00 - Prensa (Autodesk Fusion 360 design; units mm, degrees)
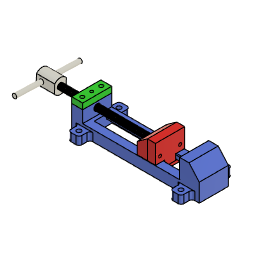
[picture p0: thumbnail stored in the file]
parameter "d29" = 2.5
sketch "Boceto1" plane through (0, 0, 0) normal (0, 1, 0) x axis (1, 0, 0)
  line L1 (175, 0) -> (0, 0)
  line L2 (0, -40) -> (0, 0)
  line L3 (15, -40) -> (0, -40)
  line L4 (15, -14) -> (15, -40)
  line L5 (151, -14) -> (15, -14)
  line L6 (151, -40) -> (151, -14)
  line L7 (161, -40) -> (151, -40)
  line L8 (175, -14) -> (175, 0)
  line L9 (175, -24) -> (175, -14)
  line L10 (161, -40) -> (175, -24)
  point P1 (0, 0)
  point P2 (0, 0)
  point P4 (0, 0)
  point P3 (175, 0)
  point P5 (0, -40)
  point P6 (15, -40)
  point P7 (15, -14)
  point P8 (151, -14)
  point P9 (151, -40)
  point P10 (161, -40)
  point P11 (175, -14)
  point P12 (175, -24)
  coincident P1 P2
  horizontal L1
  coincident P1 P4
  perpendicular L1 L2
  perpendicular L2 L3
  perpendicular L3 L4
  perpendicular L4 L5
  perpendicular L3 L6
  perpendicular L6 L7
  perpendicular L5 L8
  perpendicular L5 L9
  dimension "d1" distance P2 P3 = 175
  dimension "d2" distance P4 P5 = 40
  dimension "d3" distance P5 P6 = 15
  dimension "d4" distance P6 P7 = 26
  dimension "d5" distance P7 P8 = 136
  dimension "d7" distance P9 P10 = 10
  dimension "d8" distance P11 P12 = 10
extrude "Extruir1" new body sketch "Boceto1" along normal blind 40
sketch "Boceto2" plane through (0, 0, 14) normal (0, 0, 1) x axis (-1, 0, 0)
  line L1 (-151, 0) -> (-15, 0)
  line L2 (-151, -40) -> (-151, 0)
  line L3 (-15, -40) -> (-151, -40)
  line L4 (-15, 0) -> (-15, -40)
  line L5 (-146, -27.5) -> (-20, -27.5)
  line L6 (-146, -12.5) -> (-146, -27.5)
  line L7 (-20, -12.5) -> (-146, -12.5)
  line L8 (-20, -27.5) -> (-20, -12.5)
  line L9 (-146, -12.5) -> (-20, -27.5)
  line L10 (-20, -12.5) -> (-146, -27.5)
  line L11 (-83, 0) -> (-83, -40)
  point P10 (-83, -20)
  point P11 (-83, -40)
  point P12 (-83, 0)
  point P8 (-146, -12.5)
  point P9 (-20, -12.5)
  point P7 (-146, -27.5)
  horizontal L5
  perpendicular L5 L6
  parallel L5 L7
  parallel L6 L8
  coincident L9 P10
  coincident L10 P10
  midpoint L3 P11
  midpoint L1 P12
  midpoint P10 L11
  dimension "d11" distance P8 P9 = 126
  dimension "d12" distance P7 P8 = 15
extrude "Extruir2" cut sketch "Boceto2" profile of L5 L6 L7 L8 against normal blind 14
sketch "Boceto3" plane through (0, 0, 0) normal (-1, 0, 0) x axis (0, -1, 0)
  line L1 (0, 40) -> (0, 0)
  line L2 (-40, 40) -> (0, 40)
  line L3 (-40, 0) -> (-40, 40)
  line L4 (0, 0) -> (-40, 0)
  line L5 (-20, 23) -> (-20, 40)
  circle C1 centre (-20, 23) radius 4
  point P6 (-20, 40)
  point P7 (-20, 23)
  point P8 (-20, 23)
  midpoint L2 P6
  perpendicular L2 L5
  coincident P7 P8
  dimension "d15" distance P6 P7 = 17
  dimension "d16" diameter C1 = 8
extrude "Extruir3" cut sketch "Boceto3" profile of C1 against normal blind 15
sketch "Boceto4" plane through (0, 0, 0) normal (0, 0, -1) x axis (1, 0, 0)
  line L1 (146, -27.5) -> (146, -12.5)
  line L2 (20, -27.5) -> (146, -27.5)
  line L3 (20, -12.5) -> (20, -27.5)
  line L4 (146, -12.5) -> (20, -12.5)
  line L5 (0, 0) -> (175, 0)
  line L6 (0, -40) -> (0, 0)
  line L7 (175, -40) -> (0, -40)
  line L8 (175, 0) -> (175, -40)
  line L9 (20, -5) -> (146, -5)
  line L10 (20, -35) -> (20, -5)
  line L11 (146, -35) -> (20, -35)
  line L12 (146, -5) -> (146, -35)
  line L13 (20, -35) -> (146, -5)
  line L14 (146, -35) -> (20, -5)
  point P14 (83, -20)
  point P12 (20, -35)
  point P13 (146, -35)
  point P11 (20, -5)
  horizontal L9
  perpendicular L9 L10
  parallel L9 L11
  parallel L10 L12
  coincident L13 P14
  coincident L14 P14
  dimension "d19" distance P12 P13 = 126
  dimension "d20" distance P11 P12 = 30
extrude "Extruir4" cut sketch "Boceto4" profile of L2 L4 L9 L10 L11 L12 against normal blind 6
sketch "Boceto5" plane through (0, 0, 0) normal (0, 0, -1) x axis (1, 0, 0)
  line L1 (0, 0) -> (175, 0)
  line L2 (0, -40) -> (0, 0)
  line L3 (175, -40) -> (0, -40)
  line L4 (175, 0) -> (175, -40)
  line L5 (146, -35) -> (146, -5)
  line L6 (20, -35) -> (146, -35)
  line L7 (20, -5) -> (20, -35)
  line L8 (146, -5) -> (20, -5)
  line L9 (10, 0) -> (0, 0)
  line L10 (25, 0) -> (10, 0)
  line L11 (25, 15) -> (25, 0)
  line L12 (10, 15) -> (25, 15)
  line L13 (10, 0) -> (10, 15)
  line L14 (20, -20) -> (0, -20)
  line L15 (87.5, -5) -> (87.5, 0)
  line L16 (165, 15) -> (150, 15)
  line L17 (165, 0) -> (165, 15)
  line L18 (150, 0) -> (165, 0)
  line L19 (150, 15) -> (150, 0)
  line L20 (10, -55) -> (25, -55)
  line L21 (10, -40) -> (10, -55)
  line L22 (25, -40) -> (10, -40)
  line L23 (25, -55) -> (25, -40)
  line L24 (165, -55) -> (150, -55)
  line L25 (150, -55) -> (150, -40)
  line L26 (150, -40) -> (165, -40)
  line L27 (165, -40) -> (165, -55)
  line L28 (17.5, 0) -> (17.5, 15)
  circle C1 centre (17.5, 7.5) radius 2.5
  circle C2 centre (157.5, 7.5) radius 2.5
  circle C3 centre (17.5, -47.5) radius 2.5
  circle C4 centre (157.5, -47.5) radius 2.5
  point P1 (0, 0)
  point P10 (0, 0)
  point P11 (10, 0)
  point P16 (0, -20)
  point P17 (20, -20)
  point P18 (87.5, 0)
  point P19 (87.5, -5)
  point P22 (165, 0)
  point P12 (25, 0)
  point P23 (150, 0)
  point P13 (25, 15)
  point P20 (150, 15)
  point P14 (10, 15)
  point P21 (165, 15)
  point P27 (10, -40)
  point P28 (25, -40)
  point P25 (25, -55)
  point P26 (10, -55)
  point P30 (150, -55)
  point P31 (165, -55)
  point P33 (165, -40)
  point P32 (150, -40)
  point P35 (17.5, 15)
  point P36 (17.5, 0)
  point P15 (17.5, 7.5)
  coincident P1 P10
  coincident L1 P11
  horizontal L10
  vertical L11
  horizontal L12
  vertical L13
  midpoint L2 P16
  midpoint L7 P17
  midpoint L1 P18
  coincident L8 P19
  perpendicular L8 L15
  symmetric P11 L15 P22
  symmetric P12 L15 P23
  symmetric P13 L15 P20
  symmetric P14 L15 P21
  symmetric C1 L15 C2
  symmetric P11 L14 P27
  symmetric P12 L14 P28
  symmetric P13 L14 P25
  symmetric P14 L14 P26
  symmetric C1 L14 C3
  symmetric L14 P20 P30
  symmetric L14 P21 P31
  symmetric L14 P22 P33
  symmetric L14 P23 P32
  symmetric L14 C2 C4
  midpoint L12 P35
  midpoint L10 P36
  midpoint P15 L28
  dimension "d23" distance P10 P11 = 10
  dimension "d24" distance P11 P12 = 15
  dimension "d25" distance P11 P14 = 15
  dimension "d26" diameter C1 = 5
extrude "Extruir5" add sketch "Boceto5" profile of L1 L3 L10 L11 L12 L13 C1 L16 L17 L18 C2 L19 L20 L21 L22 C3 L23 L24 L25 L26 L27 C4 against normal blind 10
component_from_bodies "Cuerpo - > Comp.1"
sketch "Boceto1" plane through (0, 0, 0) normal (0, 1, 0) x axis (1, 0, 0)
  line L1 (0, -40) -> (0, 0)
  line L2 (-10, -40) -> (0, -40)
  line L3 (-24, 0) -> (0, 0)
  line L4 (-24, -30) -> (-24, 0)
  line L5 (-10, -40) -> (-24, -30)
  point P1 (0, 0)
  point P2 (0, 0)
  point P5 (0, 0)
  point P3 (0, -40)
  point P4 (-10, -40)
  point P6 (-24, 0)
  point P7 (-24, -30)
  coincident P1 P2
  vertical L1
  perpendicular L1 L2
  coincident P1 P5
  horizontal L3
  perpendicular L3 L4
  dimension "d30" distance P3 P4 = 10
  dimension "d31" distance P5 P6 = 24
  dimension "d32" distance P6 P7 = 30
extrude "Extruir1" new body sketch "Boceto1" along normal blind 40
sketch "Boceto6" plane through (-24, 0, 0) normal (-1, 0, 0) x axis (0, -1, 0)
  line L1 (0, 30) -> (0, 0)
  line L2 (-40, 30) -> (0, 30)
  line L3 (-40, 0) -> (-40, 30)
  line L4 (0, 0) -> (-40, 0)
  line L5 (-20, 23) -> (-20, 0)
  circle C1 centre (-20, 23) radius 4
  point P6 (-20, 0)
  point P7 (-20, 23)
  point P8 (-20, 23)
  midpoint L4 P6
  perpendicular L4 L5
  coincident P7 P8
  dimension "d35" distance P6 P7 = 23
  dimension "d36" diameter C1 = 8
extrude "Extruir2" cut sketch "Boceto6" profile of C1 against normal blind 24
sketch "Boceto2" plane through (-24, 0, 0) normal (-1, 0, 0) x axis (0, -1, 0)
  line L1 (0, 30) -> (0, 0)
  line L2 (-40, 30) -> (0, 30)
  line L3 (-40, 0) -> (-40, 30)
  line L4 (0, 0) -> (-40, 0)
  line L5 (-35, 0) -> (-20, 0)
  line L6 (-35, 6) -> (-35, 0)
  line L7 (-27.5, 6) -> (-35, 6)
  line L8 (-27.5, 14) -> (-27.5, 6)
  line L9 (-20, 14) -> (-27.5, 14)
  line L10 (-20, 0) -> (-20, 14)
  line L11 (-20, 14) -> (-12.5, 14)
  line L12 (-12.5, 6) -> (-5, 6)
  line L13 (-12.5, 14) -> (-12.5, 6)
  line L14 (-5, 6) -> (-5, 0)
  line L15 (-5, 0) -> (-20, 0)
  line L16 (-40, 14) -> (-27.5, 14)
  line L17 (0, 14) -> (-12.5, 14)
  circle C1 centre (-20, 23) radius 4
  point P7 (-20, 0)
  point P18 (-20, 0)
  point P8 (-35, 0)
  point P17 (-5, 0)
  point P9 (-35, 6)
  point P15 (-5, 6)
  point P10 (-27.5, 6)
  point P16 (-12.5, 6)
  point P11 (-27.5, 14)
  point P13 (-12.5, 14)
  point P12 (-20, 14)
  point P14 (-20, 14)
  point P19 (-40, 14)
  point P20 (-12.5, 14)
  point P21 (0, 14)
  midpoint L4 P7
  parallel L4 L5
  perpendicular L4 L6
  perpendicular L6 L7
  perpendicular L4 L8
  perpendicular L8 L9
  perpendicular L5 L10
  symmetric P7 L10 P18
  symmetric P8 L10 P17
  symmetric P9 L10 P15
  symmetric P10 L10 P16
  symmetric P11 L10 P13
  symmetric P12 L10 P14
  coincident L3 P19
  perpendicular L3 L16
  symmetric P11 L10 P20
  symmetric L10 P19 P21
  dimension "d39" distance P7 P8 = 15
  dimension "d40" distance P8 P9 = 6
  dimension "d41" distance P9 P10 = 7.5
  dimension "d42" distance P10 P11 = 8
extrude "Extruir3" cut sketch "Boceto2" profile of L1 L3 L4 L6 L7 L8 L12 L13 L14 L16 L17 against normal blind 24
position "Posición1"
ground "Fijo"
joint "Ensamblar1" alignAngle 0 alignOffsetX 0 alignOffsetY 0 alignOffsetZ 0 DistanciaMinimum -51 DistanciaMaximum 51
position "Posición2"
extrude "Extruir1" add of existing geometry blind 5
position "Posición3"
sketch "Boceto7" plane through (46.0074, 0, 0) normal (-1, 0, 0) x axis (0, -1, 0)
  line L1 (-35, 0) -> (-35, 6)
  line L2 (-5, 0) -> (-35, 0)
  line L3 (-5, 6) -> (-5, 0)
  line L4 (-12.5, 6) -> (-5, 6)
  line L5 (-12.5, 14) -> (-12.5, 6)
  line L6 (0, 14) -> (-12.5, 14)
  line L7 (0, 30) -> (0, 14)
  line L8 (-40, 30) -> (0, 30)
  line L9 (-40, 14) -> (-40, 30)
  line L10 (-27.5, 14) -> (-40, 14)
  line L11 (-27.5, 6) -> (-27.5, 14)
  line L12 (-35, 6) -> (-27.5, 6)
  line L13 (-12.5, 6) -> (-27.5, 6)
  circle C1 centre (-20, 23) radius 4
  point P13 (-27.5, 6)
  point P15 (-27.5, 6)
  point P6 (-12.5, 6)
  point P16 (-12.5, 6)
  coincident P13 P15
  coincident P6 P16
extrude "Extruir4" cut sketch "Boceto7" profile of L1 L2 L3 L4 L12 L13 against normal blind 24
sketch "Boceto8" plane through (46.0074, 0, 0) normal (-1, 0, 0) x axis (0, -1, 0)
  line L1 (-12.5, 6) -> (-27.5, 6)
  line L2 (-12.5, 14) -> (-12.5, 6)
  line L3 (0, 14) -> (-12.5, 14)
  line L4 (0, 30) -> (0, 14)
  line L5 (-40, 30) -> (0, 30)
  line L6 (-40, 14) -> (-40, 30)
  line L7 (-27.5, 14) -> (-40, 14)
  line L8 (-27.5, 6) -> (-27.5, 14)
  line L9 (-35, 6) -> (-27.5, 6)
  line L10 (-35, 0) -> (-35, 6)
  line L11 (-12.5, 6) -> (-27.5, 6)
  line L12 (-5, 6) -> (-12.5, 6)
  line L13 (-5, 0) -> (-5, 6)
  line L14 (-5, 0) -> (-35, 0)
  circle C1 centre (-20, 23) radius 4
  point P3 (-27.5, 6)
  point P11 (-27.5, 6)
  point P4 (-12.5, 6)
  point P14 (-12.5, 6)
  point P15 (-12.5, 6)
  point P12 (-35, 6)
  point P16 (-5, 6)
  coincident P3 P11
  perpendicular L2 L9
  perpendicular L9 L10
  coincident P4 P14
  coincident P4 P15
  perpendicular L8 L12
  perpendicular L12 L13
  perpendicular L13 L14
  dimension "d55" distance P11 P12 = 7.5
  dimension "d56" distance P15 P16 = 7.5
extrude "Extruir1" new body sketch "Boceto8" profile of L1 L9 L10 L11 L12 L13 L14 against normal blind 24
joint "Ensamblar2" alignAngle 0 alignOffsetX 0 alignOffsetY 0 alignOffsetZ 0
position "Posición4"
sketch "Boceto9" plane through (0, 0, 0) normal (0, 0, -1) x axis (1, 0, 0)
  line L1 (46.0074, -35) -> (46.0074, -5)
  line L2 (70.0074, -35) -> (46.0074, -35)
  line L3 (70.0074, -5) -> (70.0074, -35)
  line L4 (46.0074, -5) -> (70.0074, -5)
  line L5 (52.0074, -20) -> (46.0074, -20)
  line L6 (64.0074, -20) -> (70.0074, -20)
  circle C1 centre (52.0074, -20) radius 2
  circle C2 centre (64.0074, -20) radius 2
  point P6 (46.0074, -20)
  point P8 (70.0074, -20)
  point P7 (52.0074, -20)
  point P10 (52.0074, -20)
  point P9 (64.0074, -20)
  point P11 (64.0074, -20)
  midpoint L1 P6
  perpendicular L1 L5
  midpoint L3 P8
  perpendicular L3 L6
  coincident P7 P10
  coincident P9 P11
  dimension "d63" distance P6 P7 = 6
  dimension "d64" distance P8 P9 = 6
  dimension "d65" diameter C1 = 4
  dimension "d66" diameter C2 = 4
extrude "Extruir5" cut sketch "Boceto9" profile of C1 C2 against normal blind 15
position "Posición5" sketch "Boceto6"
sketch "Boceto10" plane through (0, 0, 0) normal (0, 1, 0) x axis (1, 0, 0)
  circle C1 centre (0, 30) radius 10
  dimension "d74" diameter C1 = 20
extrude "Extruir6" new body sketch "Boceto10" along normal blind 25
sketch "Boceto11" plane through (0, 0, 0) normal (0, -1, 0) x axis (1, 0, 0)
  circle C1 centre (0, -30) radius 10
  circle C2 centre (0, -30) radius 4
  concentric C1 C2
  dimension "d77" diameter C2 = 8
extrude "Extruir7" cut sketch "Boceto11" profile of C2 against normal blind 10
sketch "Boceto12" plane through (0, 0, 0) normal (0, -1, 0) x axis (1, 0, 0)
  line L1 (-8, -20) -> (8, -20)
  line L2 (-8, -40) -> (-8, -20)
  line L3 (8, -40) -> (-8, -40)
  line L4 (8, -20) -> (8, -40)
  line L5 (-8, -40) -> (8, -20)
  line L6 (8, -40) -> (-8, -20)
  circle C1 centre (0, -30) radius 4
  circle C2 centre (0, -30) radius 10
  point P7 (0, -30)
  point P2 (0, -30)
  point P5 (-8, -40)
  point P6 (8, -40)
  point P4 (-8, -20)
  horizontal L1
  perpendicular L1 L2
  parallel L1 L3
  parallel L2 L4
  coincident L5 P7
  coincident L6 P7
  coincident P2 P7
  dimension "d80" distance P5 P6 = 16
  dimension "d81" distance P4 P5 = 20
extrude "Extruir8" cut sketch "Boceto12" profile of C2 L2 L4 against normal blind 25
sketch "Boceto13" plane through (-8, 0, 0) normal (-1, 0, 0) x axis (0, -1, 0)
  line L1 (0, -24) -> (0, -36)
  line L2 (-25, -24) -> (0, -24)
  line L3 (-25, -36) -> (-25, -24)
  line L4 (0, -36) -> (-25, -36)
  line L5 (-18, -30) -> (-25, -30)
  circle C1 centre (-18, -30) radius 3
  point P6 (-25, -30)
  point P7 (-18, -30)
  point P8 (-18, -30)
  midpoint L3 P6
  perpendicular L3 L5
  coincident P7 P8
  dimension "d84" distance P6 P7 = 7
  dimension "d85" diameter C1 = 6
extrude "Extruir9" cut sketch "Boceto13" profile of C1 against normal blind 16
component_from_bodies "Cuerpo - > Comp.2"
sketch "Boceto1" plane through (0, 0, 0) normal (0, 1, 0) x axis (1, 0, 0)
  circle C1 centre (-100, 0) radius 3
  dimension "d92" diameter C1 = 6
extrude "Extruir1" new body sketch "Boceto1" along normal blind 90
joint "Ensamblar4" alignAngle 90 alignOffsetX 0 alignOffsetY 0 alignOffsetZ 0
sketch "Boceto14" plane through (54.8598, 0, 0) normal (-1, 0, 0) x axis (0, -1, 0)
  line L1 (-12.5, 6) -> (-27.5, 6)
  line L2 (-12.5, 14) -> (-12.5, 6)
  line L3 (0, 14) -> (-12.5, 14)
  line L4 (0, 30) -> (0, 14)
  line L5 (-40, 30) -> (0, 30)
  line L6 (-40, 14) -> (-40, 30)
  line L7 (-27.5, 14) -> (-40, 14)
  line L8 (-27.5, 6) -> (-27.5, 14)
  line L9 (-33.75, 30) -> (-33.75, 14)
  line L10 (-6.25, 30) -> (-6.25, 14)
  circle C1 centre (-20, 23) radius 4
  circle C2 centre (-33.75, 22) radius 2
  circle C3 centre (-6.25, 22) radius 2
  point P11 (-33.75, 14)
  point P12 (-33.75, 30)
  point P13 (-6.25, 14)
  point P14 (-6.25, 30)
  point P15 (-33.75, 22)
  point P16 (-6.25, 22)
  midpoint L7 P11
  coincident L5 P12
  perpendicular L5 L9
  midpoint L3 P13
  coincident L5 P14
  perpendicular L5 L10
  midpoint L9 P15
  midpoint L10 P16
  dimension "d99" diameter C2 = 4
  dimension "d100" diameter C3 = 4
extrude "Extruir6" cut sketch "Boceto14" profile of L9 L10 C2 C3 against normal blind 24
sketch "Boceto15" plane through (0, 0, 0) normal (0, -1, 0) x axis (1, 0, 0)
  line L1 (78.8598, 14) -> (54.8598, 14)
  line L2 (78.8598, 40) -> (78.8598, 14)
  line L3 (68.8598, 40) -> (78.8598, 40)
  line L4 (54.8598, 30) -> (68.8598, 40)
  line L5 (54.8598, 14) -> (54.8598, 30)
  line L6 (68.8598, 5) -> (68.8598, 40)
  line L7 (69.8598, 40) -> (68.8598, 40)
  line L8 (69.8598, 2) -> (69.8598, 40)
  line L9 (69.8598, 2) -> (68.8598, 5)
  point P5 (68.8598, 40)
  point P7 (68.8598, 40)
  point P9 (69.8598, 40)
  coincident P5 P7
  perpendicular L3 L6
  perpendicular L6 L7
  perpendicular L7 L8
  dimension "d103" distance P7 P9 = 1
extrude "Extruir7" cut sketch "Boceto15" profile of L1 L3 L6 L7 L8 L9 against normal blind 40
component_from_bodies "Cuerpo - > Comp.1"
position "Posición7"
copy_paste "CortarPegar"
position "Posición8"
extrude "Extruir1" add of existing geometry blind 1
joint "Ensamblar5" alignAngle 0 alignOffsetX 0 alignOffsetY 0 alignOffsetZ 0
position "Posición9"
sketch "Boceto16" plane through (90.8228, 0, 0) normal (-1, 0, 0) x axis (0, -1, 0)
  line L1 (-27.5, 14) -> (-40, 14)
  line L2 (-27.5, 6) -> (-27.5, 14)
  line L3 (-12.5, 6) -> (-27.5, 6)
  line L4 (-12.5, 14) -> (-12.5, 6)
  line L5 (0, 14) -> (-12.5, 14)
  line L6 (0, 40) -> (0, 14)
  line L7 (-40, 40) -> (0, 40)
  line L8 (-40, 14) -> (-40, 40)
  circle C1 centre (-33.75, 22) radius 2
  circle C2 centre (-6.25, 22) radius 2
  circle C3 centre (-20, 23) radius 4
  circle C4 centre (-20, 23) radius 8.5
  concentric C3 C4
  dimension "d116" diameter C4 = 17
extrude "Extruir2" cut sketch "Boceto16" profile of C3 C4 against normal blind 7
extrude "Extruir3" add of existing geometry blind 1
extrude "Extruir3" add of existing geometry blind 1
sketch "Boceto17" plane through (-3.0644, 0, 0) normal (-1, 0, 0) x axis (0, -1, 0)
  line L1 (0, 40) -> (0, 0)
  line L2 (-40, 40) -> (0, 40)
  line L3 (-40, 0) -> (-40, 40)
  line L4 (0, 0) -> (-40, 0)
  line L5 (-28.0829, 23) -> (-24.0415, 30)
  line L6 (-24.0415, 16) -> (-28.0829, 23)
  line L7 (-15.9585, 16) -> (-24.0415, 16)
  line L8 (-11.9171, 23) -> (-15.9585, 16)
  line L9 (-15.9585, 30) -> (-11.9171, 23)
  line L10 (-24.0415, 30) -> (-15.9585, 30)
  circle C1 centre (-20, 23) radius 4
  point P2 (-20, 23)
  point P13 (-20, 23)
  coincident P2 P13
  dimension "d123" distance P13 L10 = 7
extrude "Extruir2" cut sketch "Boceto17" profile of C1 L5 L6 L7 L8 L9 L10 against normal blind 11 and against normal blind 4
extrude "Extruir3" cut of existing geometry blind -10
extrude "Extruir4" cut of existing geometry blind -4.041
extrude "Extruir5" cut of existing geometry blind -4.041
extrude "Extruir6" cut of existing geometry blind -7
base_feature "Elemento base1"
joint "Ensamblar9" alignAngle 180 alignOffsetX 0 alignOffsetY 0 alignOffsetZ 0.5
joint "Ensamblar10" alignAngle 90 alignOffsetX 0 alignOffsetY 0 alignOffsetZ 0
position "Posición11"
sketch "Boceto18" plane through (0, 0, 0) normal (0, 1, 0) x axis (1, 0, 0)
  line L1 (-142.4944, 0) -> (-146.2472, -6.5)
  line L2 (-146.2472, 6.5) -> (-142.4944, 0)
  line L3 (-153.7528, 6.5) -> (-146.2472, 6.5)
  line L4 (-157.5056, 0) -> (-153.7528, 6.5)
  line L5 (-153.7528, -6.5) -> (-157.5056, 0)
  line L6 (-146.2472, -6.5) -> (-153.7528, -6.5)
  point P8 (-150, 0)
  dimension "d152" distance P8 L6 = 6.5 (= "( 13 / 2 ) * 1 mm")
extrude "Extruir10" new body sketch "Boceto18" along normal blind 6.5
sketch "Boceto19" plane through (0, 0, 0) normal (0, -1, 0) x axis (1, 0, 0)
  line L1 (-153.7528, 6.5) -> (-146.2472, 6.5)
  line L2 (-157.5056, 0) -> (-153.7528, 6.5)
  line L3 (-153.7528, -6.5) -> (-157.5056, 0)
  line L4 (-146.2472, -6.5) -> (-153.7528, -6.5)
  line L5 (-142.4944, 0) -> (-146.2472, -6.5)
  line L6 (-146.2472, 6.5) -> (-142.4944, 0)
  circle C1 centre (-150, 0) radius 4
  dimension "d155" diameter C1 = 8
extrude "Extruir11" cut sketch "Boceto19" profile of C1 against normal blind 6.5
thread "Rosca"
component_from_bodies "Cuerpo - > Comp.3"
joint "Ensamblar11" alignAngle 90 alignOffsetX 0 alignOffsetY 0 alignOffsetZ 0
position "Posición12"
extrude "Extruir7" cut of existing geometry blind -2
offset_faces "CarasDesfase1" distance -0.5
offset_faces "CarasDesfase1" distance -0.5
offset_faces "CarasDesfase2" distance -0.5
offset_faces "CarasDesfase3" distance -0.5
offset_faces "CarasDesfase4" distance -0.5
offset_faces "CarasDesfase1" distance -0.5
offset_faces "CarasDesfase2" distance -0.5
fillet "Empalme1" radius 4
fillet "Empalme2" radius 1
offset_faces "CarasDesfase5" distance -0.5
position "Posición13"
extrude "Extruir8" cut of existing geometry blind -10
extrude "Extruir1" new body of existing geometry blind 8
sketch "Boceto20" plane through (0, 0, 38) normal (0, 0, 1) x axis (-1, 0, 0)
  line L1 (-0.9356, -28.0825) -> (-0.9356, -11.9175)
  line L2 (-7.9356, -28.0825) -> (-0.9356, -28.0825)
  line L3 (-7.9356, -11.9175) -> (-7.9356, -28.0825)
  line L4 (-0.9356, -11.9175) -> (-7.9356, -11.9175)
  line L5 (-11.9356, 0) -> (3.0644, 0)
  line L6 (-11.9356, -40) -> (-11.9356, 0)
  line L7 (3.0644, -40) -> (-11.9356, -40)
  line L8 (3.0644, 0) -> (3.0644, -40)
extrude "Extruir2" add sketch "Boceto20" profile of L1 L2 L3 L4 against normal blind 5
sketch "Boceto21" plane through (0, 0, 38) normal (0, 0, 1) x axis (-1, 0, 0)
  line L1 (-11.9356, 0) -> (3.0644, 0)
  line L2 (-11.9356, -40) -> (-11.9356, 0)
  line L3 (3.0644, -40) -> (-11.9356, -40)
  line L4 (3.0644, 0) -> (3.0644, -40)
  line L5 (-4.4356, -7) -> (-4.4356, 0)
  line L6 (-4.4356, -33) -> (-4.4356, -40)
  circle C1 centre (-4.4356, -20) radius 2
  circle C2 centre (-4.4356, -33) radius 2
  circle C3 centre (-4.4356, -7) radius 2
  point P7 (-4.4356, 0)
  point P9 (-4.4356, -40)
  point P10 (-4.4356, -33)
  point P11 (-4.4356, -33)
  point P8 (-4.4356, -7)
  point P12 (-4.4356, -7)
  midpoint L1 P7
  perpendicular L1 L5
  midpoint L3 P9
  perpendicular L3 L6
  coincident P10 P11
  coincident P8 P12
  dimension "d182" diameter C1 = 4
  dimension "d183" distance P9 P10 = 7
  dimension "d184" diameter C2 = 4
  dimension "d185" diameter C3 = 4
extrude "Extruir9" cut sketch "Boceto21" profile of C2 C3 against normal blind 16
extrude "Extruir4" cut sketch "Boceto21" profile of C1 against normal blind 8
offset_faces "CarasDesfase1" distance -0.5
offset_faces "CarasDesfase6" distance -0.5
position "Posición14"
motion_link "VínculoDeMovimiento" Value1 360 Value2 1.25
position "Posición15"
extrude "Extruir10" cut of existing geometry blind -4
extrude "Extruir4" cut of existing geometry blind -2
extrude "Extruir11" add of existing geometry blind 1
position "Posición16"
sketch "Boceto22" plane through (111.9773, 0, 0) normal (1, 0, 0) x axis (0, 1, 0)
  line L1 (27.5, 6) -> (12.5, 6)
  line L2 (27.5, 14) -> (27.5, 6)
  line L3 (40, 14) -> (27.5, 14)
  line L4 (40, 40) -> (40, 14)
  line L5 (0, 40) -> (40, 40)
  line L6 (0, 14) -> (0, 40)
  line L7 (12.5, 14) -> (0, 14)
  line L8 (12.5, 6) -> (12.5, 14)
  circle C1 centre (33.75, 22) radius 2
  circle C2 centre (6.25, 22) radius 2
  circle C3 centre (20, 23) radius 4
extrude "Extruir4" add sketch "Boceto22" profile of C3 against normal blind 4
offset_faces "CarasDesfase7" distance -0.5
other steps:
base_feature "Elemento base1"
base_feature "Elemento base1"
base_feature "Elemento base1"
extrude "Extruir2" cut sketch "Boceto9" profile of C1 C2 against normal blind 15
base_feature "Elemento base1"
extrude "Extruir3" cut sketch "Boceto21" profile of C2 C3 against normal blind 16
create_component "CrearComponentes1"
remove_body "QuitarCuerpo1"
create_component "CrearComponentes2"
joint_origin "OrigenDeLaUnión1"
joint_origin "OrigenDeLaUnión1"
create_component "CrearComponentes3"
joint_origin "OrigenDeLaUnión1"
joint_origin "OrigenDeLaUnión2"
create_component "CrearComponentes6"
remove_body "QuitarCuerpo2"
create_component "CrearComponentes7"
joint_origin "OrigenDeLaUnión1"
joint_origin "OrigenDeLaUnión2"
create_component "CrearComponentes1"
remove_body "QuitarCuerpo1"
remove_instance "EliminarInstancia"
joint_origin "OrigenDeLaUnión3"
joint_origin "OrigenDeLaUnión2"
create_component "CrearComponentes9"
joint_origin "OrigenDeLaUnión1"
joint_origin "OrigenDeLaUnión4"
joint_origin "OrigenDeLaUnión4"
joint_origin "OrigenDeLaUnión2"
create_component "CrearComponentes10"
remove_body "QuitarCuerpo3"
joint_origin "OrigenDeLaUnión1"
joint_origin "OrigenDeLaUnión4"
create_component "CrearComponentes11"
